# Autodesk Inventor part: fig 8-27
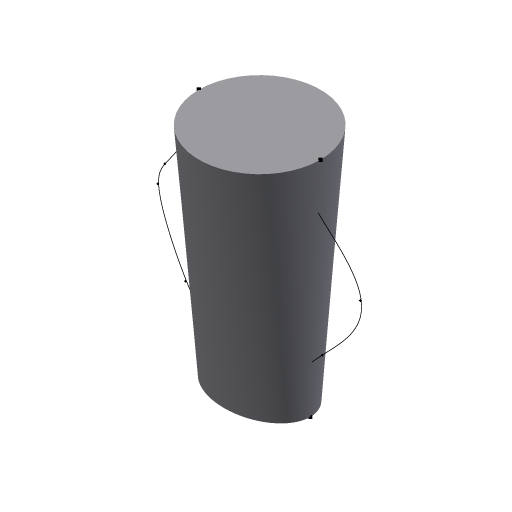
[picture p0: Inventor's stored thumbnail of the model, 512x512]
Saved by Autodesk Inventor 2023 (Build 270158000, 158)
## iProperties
Part Number: fig 8-27
Document SubType Name: Modeling
Created: 2002-12
Designer: deepak
Density: 1 g/cm^3
Material: Generic
Appearance: Default
Control State: 0
Master: False
Checked Out: False
Shininess: 64.0
Length Units: 11269
Angle Units: 11279
Time Units: 11290
Mass Units: 11283
Length Display Precision: 3
Angle Display Precision: 2
Compacted: True
Density: 0.0
Volumn: 0.0
Area: 0.0
PropertySet Name: Model Information
Author: deepak
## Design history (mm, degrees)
sketch "Sketch1"
  geometry: 2 further points; 1 other entity
  constraints: 1 coincident, 3 other
workplane "Work Plane1"
workplane "Work Plane2"
sketch "Sketch3"
  geometry: C1 r 60 at (0, 0); 1 further point
  constraints: 1 centre point, 1 coincident, 1 other
sketch "Sketch4"
  geometry: 8 further points
  constraints: 8 other
sketch "Sketch5"
  geometry: 6 further points
  constraints: 6 other
sketch "Sketch6"
  geometry: 6 further points
  constraints: 6 other
  dimensions: "d20" = 35 distance of point (0, 0) point (-35, 0); "d21" = 0 vertical distance of point (0, 0) point (-35, 0); "d22" = 225 vertical distance of point (0, 0) point (-60, 225); "d23" = 60 horizontal distance of point (0, 0) point (-60, 225); "d24" = 100 horizontal distance of point (0, 0) point (-100, 125); "d25" = 125 vertical distance of point (0, 0) point (-100, 125)
loft "Loft4" dims "d50" = 0, "d51" = 90 deg, "d52" = 0, "d53" = 90 deg
body "Solid1"
other parameters: "d5" = 125
